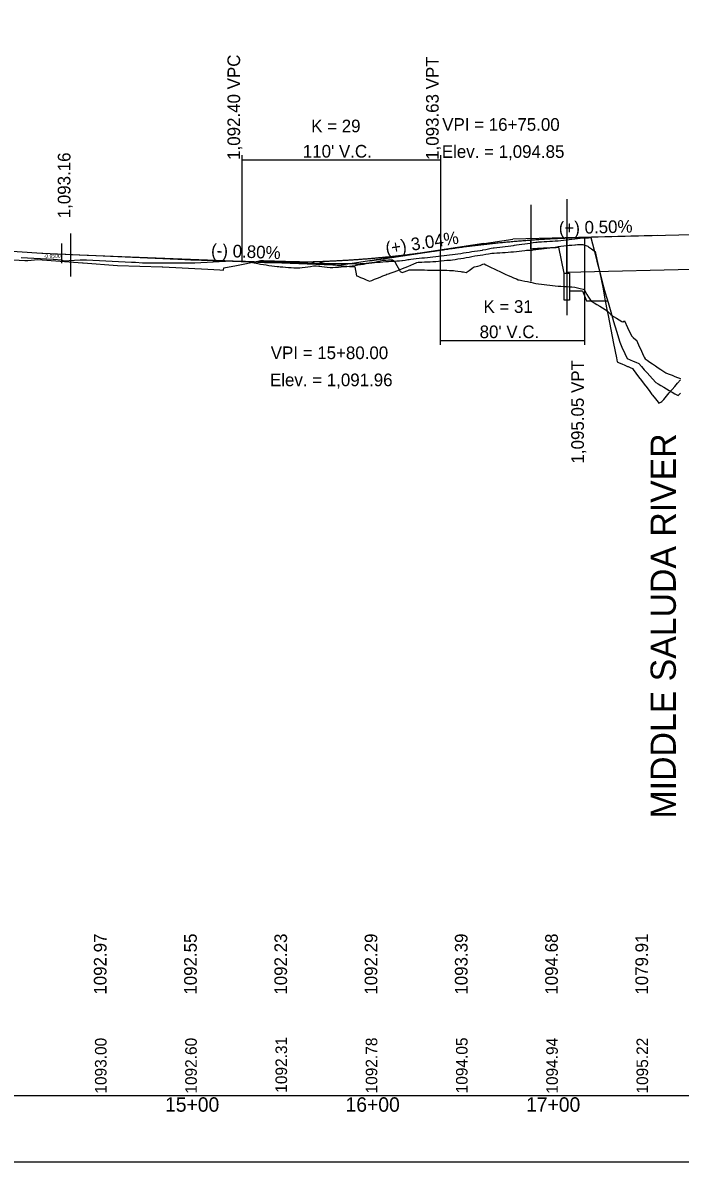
# Model space of a CAD drawing. Extents: x 1545155 to 1547500, y 1196198 to 1197298.
# Drawn here: x 1545559 to 1545923, y 1196198 to 1196829 of the extents above; entities that cross this region are included whole.
import ezdxf

# ---------------------------------------------------------------- set-up
doc = ezdxf.new("R2010")
doc.units = 0
for name, color, linetype in [('BR_CONCRETE', 7, 'Continuous'), ('BR_PROPOSED_TRAVELWAY', 7, 'Continuous'), ('RD_PD_ALT1_TX', 7, 'Continuous'), ('RD_PD_BOC', 7, 'Continuous'), ('RD_PD_CstnLmt', 7, 'Continuous'), ('RD_PD_DR_ErosCtrl', 7, 'Continuous'), ('RD_PD_Final_TrvlWay', 7, 'Continuous'), ('RD_PD_PaveShd', 7, 'Continuous'), ('RD_PD_RW_TX', 7, 'Continuous'), ('RD_SHT_IplotShp', 7, 'Continuous'), ('RD_SHT_ShtClip', 7, 'Continuous'), ('RD_Sketch1', 7, 'Continuous'), ('RD_Sketch2', 7, 'Continuous'), ('RD_Sketch8', 7, 'Continuous')]:
    doc.layers.add(name, color=color, linetype=linetype)

msp = doc.modelspace()

# ---------------------------------------------------------------- linework, layer by layer
at = {"layer": 'BR_CONCRETE'}
msp.add_lwpolyline([(1545544.44, 1196703.26), (1545569.25, 1196701.73), (1545569.73, 1196701.7), (1545594.31, 1196700.54), (1545594.64, 1196700.53), (1545595.08, 1196700.5), (1545619.42, 1196699.35), (1545644.41, 1196698.29), (1545645.07, 1196698.26), (1545651.75, 1196698.04), (1545669.53, 1196697.42), (1545670.23, 1196697.41), (1545688.8, 1196696.71), (1545690.34, 1196696.65), (1545691.88, 1196696.59), (1545692.6, 1196696.56), (1545693.42, 1196696.56), (1545694.99, 1196696.55), (1545696.5, 1196696.52), (1545698.04, 1196696.49), (1545699.58, 1196696.45), (1545701.12, 1196696.42), (1545702.66, 1196696.38), (1545704.2, 1196696.35), (1545705.74, 1196696.31), (1545707.28, 1196696.28), (1545708.82, 1196696.24), (1545710.36, 1196696.2), (1545711.9, 1196696.16), (1545713.44, 1196696.12), (1545714.98, 1196696.08), (1545716.52, 1196696.04), (1545717.54, 1196696.02), (1545718.06, 1196696.01), (1545718.74, 1196696.01), (1545719.6, 1196695.98), (1545720.08, 1196695.97), (1545721.14, 1196695.97), (1545722.68, 1196695.96), (1545724.22, 1196695.95), (1545725.76, 1196695.95), (1545727.3, 1196695.94), (1545728.84, 1196695.93), (1545730.38, 1196695.92), (1545731.92, 1196695.91), (1545733.46, 1196695.9), (1545735, 1196695.89), (1545736.54, 1196695.88), (1545738.08, 1196695.87), (1545739.62, 1196695.86), (1545741.16, 1196695.84), (1545742.7, 1196695.83), (1545744.24, 1196695.82), (1545744.71, 1196695.81), (1545745.07, 1196695.81), (1545745.78, 1196695.86), (1545747.32, 1196696), (1545748.86, 1196696.13), (1545750.4, 1196696.27), (1545751.94, 1196696.39), (1545753.48, 1196696.52), (1545755.02, 1196696.64), (1545756.56, 1196696.76), (1545758.1, 1196696.87), (1545759.64, 1196696.99), (1545761.18, 1196697.09), (1545762.72, 1196697.2), (1545764.26, 1196697.3), (1545765.8, 1196697.4), (1545767.34, 1196697.49), (1545768.55, 1196697.56), (1545768.88, 1196697.61), (1545770.42, 1196697.85), (1545771.96, 1196698.07), (1545772.73, 1196698.19), (1545773.5, 1196698.28), (1545775.04, 1196698.46), (1545776.58, 1196698.64), (1545778.12, 1196698.81), (1545779.66, 1196698.98), (1545781.2, 1196699.15), (1545782.74, 1196699.32), (1545784.28, 1196699.49), (1545785.82, 1196699.65), (1545787.36, 1196699.81), (1545788.9, 1196699.97), (1545790.44, 1196700.12), (1545791.99, 1196700.28), (1545793.53, 1196700.48), (1545795.07, 1196700.67), (1545796.61, 1196700.87), (1545798.16, 1196701.06), (1545799.69, 1196701.31), (1545801.23, 1196701.56), (1545802.77, 1196701.8), (1545804.31, 1196702.05), (1545805.85, 1196702.28), (1545807.39, 1196702.52), (1545808.93, 1196702.75), (1545810.47, 1196702.99), (1545812.01, 1196703.21), (1545813.21, 1196703.39), (1545813.55, 1196703.46), (1545815.09, 1196703.76), (1545816.63, 1196704.06), (1545818.17, 1196704.36), (1545819.27, 1196704.58), (1545819.79, 1196704.65), (1545821.25, 1196704.84), (1545822.79, 1196705.03), (1545824.33, 1196705.22), (1545825.87, 1196705.41), (1545827.41, 1196705.6), (1545828.95, 1196705.78), (1545830.49, 1196705.96), (1545830.99, 1196706.02), (1545832.03, 1196706.18), (1545833.57, 1196706.4), (1545835.11, 1196706.62), (1545836.65, 1196706.84), (1545838.19, 1196707.06), (1545839.73, 1196707.28), (1545841.27, 1196707.49), (1545842.81, 1196707.7), (1545843.6, 1196707.81), (1545844.35, 1196707.86), (1545845.89, 1196707.97), (1545847.43, 1196708.08), (1545848.97, 1196708.18), (1545850.51, 1196708.28), (1545852.05, 1196708.38), (1545853.59, 1196708.48), (1545855.13, 1196708.57), (1545856.67, 1196708.67), (1545858.21, 1196708.77), (1545859.75, 1196708.96), (1545861.29, 1196709.16), (1545862.83, 1196709.35), (1545864.37, 1196709.55), (1545865.91, 1196709.74), (1545867.45, 1196709.93), (1545868.58, 1196710.07), (1545868.99, 1196710.1), (1545869.47, 1196710.12), (1545870.53, 1196710.17), (1545872.07, 1196710.23), (1545872.52, 1196710.25), (1545873.34, 1196710.35), (1545875.15, 1196703.25), (1545876.69, 1196697.2), (1545878.23, 1196691.16), (1545879.99, 1196684.22), (1545881.31, 1196679.69), (1545882.85, 1196674.39), (1545884.39, 1196669.1), (1545885.93, 1196663.8), (1545887.47, 1196658.52), (1545889.28, 1196652.3), (1545890.55, 1196649.53), (1545892.09, 1196646.17), (1545893.43, 1196643.25), (1545895.17, 1196642.52), (1545896.71, 1196641.88), (1545898.25, 1196641.23), (1545899.87, 1196640.49), (1545901.33, 1196638.86), (1545902.87, 1196637.13), (1545904.41, 1196635.41), (1545905.95, 1196633.69), (1545907.49, 1196631.97), (1545909.25, 1196630.01), (1545910.57, 1196629.22), (1545912.11, 1196628.31), (1545913.65, 1196627.4), (1545915.19, 1196626.49), (1545916.73, 1196625.59), (1545918.27, 1196624.69), (1545919.81, 1196623.8), (1545921.6, 1196622.76), (1545922.89, 1196624.18)], dxfattribs=at)
at = {"layer": 'BR_PROPOSED_TRAVELWAY'}
msp.add_lwpolyline([(1545155, 1197298.22), (1546955, 1197298.22), (1546955, 1196198.22), (1545155, 1196198.22)], close=True, dxfattribs=at)
at = {"layer": 'RD_PD_ALT1_TX'}
msp.add_lwpolyline([(1545547.12, 1196698.3), (1545559.78, 1196697.58), (1545561.36, 1196697.58), (1545566.99, 1196698.17), (1545591.6, 1196696.23), (1545592.05, 1196696.27), (1545611.05, 1196694.79), (1545635.73, 1196694.16), (1545636.19, 1196694.13), (1545661.04, 1196692.75), (1545667.86, 1196692.37), (1545669.71, 1196692.32), (1545670.04, 1196693.57), (1545676.97, 1196694.79), (1545688.8, 1196697.23), (1545690.36, 1196697.58), (1545691.88, 1196697.53), (1545693.42, 1196697.48), (1545694.96, 1196697.43), (1545696.5, 1196697.39), (1545698.04, 1196697.34), (1545699.58, 1196697.29), (1545701.12, 1196697.25), (1545702.66, 1196697.2), (1545704.2, 1196697.16), (1545705.74, 1196697.12), (1545707.28, 1196697.07), (1545708.82, 1196697.03), (1545710.36, 1196696.99), (1545711.9, 1196696.95), (1545713.44, 1196696.91), (1545714.98, 1196696.86), (1545716.52, 1196696.82), (1545718.1, 1196696.78), (1545719.6, 1196696.31), (1545721.14, 1196695.8), (1545721.9, 1196695.53), (1545722.68, 1196695.33), (1545723.05, 1196695.23), (1545723.39, 1196696.57), (1545724.22, 1196696.43), (1545725.76, 1196696.17), (1545727.3, 1196695.91), (1545728.84, 1196695.65), (1545730.38, 1196695.4), (1545731.92, 1196695.14), (1545733.46, 1196694.88), (1545735.2, 1196694.59), (1545736.54, 1196694.5), (1545738.08, 1196694.41), (1545739.62, 1196694.31), (1545741.16, 1196694.22), (1545742.57, 1196694.14), (1545743.46, 1196689.15), (1545744.24, 1196688.83), (1545745.78, 1196688.19), (1545747.32, 1196687.54), (1545748.86, 1196686.88), (1545750.64, 1196686.1), (1545751.94, 1196686.58), (1545753.48, 1196687.17), (1545755.02, 1196687.77), (1545756.56, 1196688.39), (1545758.1, 1196689.03), (1545759.64, 1196689.68), (1545760.23, 1196689.94), (1545761.18, 1196690.26), (1545762.72, 1196690.79), (1545764.26, 1196691.34), (1545765.8, 1196691.9), (1545767.34, 1196692.48), (1545768.88, 1196693.07), (1545770.42, 1196693.69), (1545771.96, 1196694.32), (1545773.5, 1196694.96), (1545775.25, 1196695.72), (1545776.58, 1196696.36), (1545776.94, 1196696.53), (1545777.57, 1196696.72), (1545778.12, 1196696.72), (1545779.66, 1196696.75), (1545781.2, 1196696.8), (1545782.74, 1196696.85), (1545784.28, 1196696.93), (1545785.82, 1196697.02), (1545787.36, 1196697.12), (1545788.9, 1196697.24), (1545790.44, 1196697.38), (1545791.99, 1196697.52), (1545793.53, 1196697.69), (1545794.1, 1196697.76), (1545795.07, 1196697.83), (1545795.46, 1196697.86), (1545796.61, 1196698.01), (1545798.15, 1196698.22), (1545799.69, 1196698.45), (1545801.23, 1196698.7), (1545802.77, 1196698.96), (1545804.31, 1196699.23), (1545805.85, 1196699.52), (1545807.39, 1196699.83), (1545809.06, 1196700.18), (1545810.47, 1196700.37), (1545812.01, 1196700.58), (1545813.55, 1196700.8), (1545815.09, 1196701.03), (1545816.63, 1196701.27), (1545818.41, 1196701.59), (1545819.71, 1196701.66), (1545821.25, 1196701.76), (1545822.79, 1196701.86), (1545824.33, 1196701.97), (1545825.87, 1196702.08), (1545827.41, 1196702.21), (1545828.95, 1196702.34), (1545830.49, 1196702.48), (1545832.03, 1196702.63), (1545833.57, 1196702.79), (1545835.11, 1196702.95), (1545836.65, 1196703.12), (1545837.7, 1196703.24), (1545838.19, 1196703.26), (1545839.73, 1196703.32), (1545840.77, 1196703.37), (1545841.27, 1196703.43), (1545842.81, 1196703.61), (1545844.35, 1196703.8), (1545845.89, 1196703.99), (1545847.43, 1196704.19), (1545848.97, 1196704.4), (1545850.51, 1196704.61), (1545852.05, 1196704.82), (1545853.59, 1196705.04), (1545855.13, 1196705.27), (1545856.67, 1196705.5), (1545858.29, 1196705.76), (1545859.75, 1196705.88), (1545861.29, 1196706.02), (1545862.83, 1196706.16), (1545864.37, 1196706.3), (1545864.85, 1196706.35), (1545865.91, 1196706.39), (1545867.45, 1196706.47), (1545868.85, 1196706.54), (1545870.53, 1196705.9), (1545871.7, 1196705.46), (1545872.07, 1196705.19), (1545873.61, 1196704.08), (1545875.15, 1196703), (1545875.78, 1196702.56), (1545876.69, 1196698.19), (1545878.23, 1196690.76), (1545879.86, 1196682.89), (1545881.31, 1196675.24), (1545882.39, 1196669.54), (1545882.85, 1196667.19), (1545884.39, 1196659.36), (1545885.93, 1196651.54), (1545887.47, 1196643.73), (1545887.91, 1196641.47), (1545889.01, 1196640.99), (1545890.55, 1196640.32), (1545892.09, 1196639.65), (1545893.63, 1196638.98), (1545893.98, 1196638.83), (1545895.17, 1196638.3), (1545896.29, 1196637.79), (1545896.71, 1196637.24), (1545898.25, 1196635.2), (1545899.79, 1196633.15), (1545901.33, 1196631.11), (1545902.87, 1196629.07), (1545904.41, 1196627.04), (1545905.95, 1196625.01), (1545907.17, 1196623.4), (1545907.49, 1196623), (1545909.03, 1196621.05), (1545910.57, 1196619.1), (1545911.02, 1196618.53), (1545912.11, 1196619.16), (1545912.71, 1196619.51), (1545913.65, 1196620.62), (1545915.19, 1196622.44), (1545916.73, 1196624.26), (1545918.27, 1196626.07), (1545919.81, 1196627.88), (1545921.35, 1196629.69), (1545922.89, 1196631.5)], dxfattribs=at)
at = {"layer": 'RD_PD_BOC'}
for p, q in [((1545839.97, 1196704.11), (1545839.97, 1196708.96)), ((1545860, 1196691.01), (1545860, 1196710.1)), ((1545858.5, 1196690.6), (1545855.64, 1196704.94)), ((1545860, 1196691.07), (1545960, 1196693.57)), ((1545860, 1196691.01), (1545860, 1196690.6)), ((1545861.5, 1196680.78), (1545868.59, 1196680.78)), ((1545868.59, 1196680.78), (1545870.83, 1196675.18)), ((1545870.83, 1196675.18), (1545882.62, 1196675.18))]:
    msp.add_line(p, q, dxfattribs=at)
msp.add_lwpolyline([(1545858.5, 1196690.6), (1545861.5, 1196690.6), (1545861.5, 1196675.6), (1545858.5, 1196675.6)], close=True, dxfattribs=at)
msp.add_open_spline([(1545839.97, 1196704.11), (1545841.69, 1196704.22), (1545843.41, 1196704.33), (1545848.45, 1196704.62), (1545851.76, 1196704.78), (1545855.27, 1196704.92), (1545855.45, 1196704.93), (1545855.64, 1196704.94)], degree=3, dxfattribs=at)
at = {"layer": 'RD_PD_DR_ErosCtrl'}
for p, q in [((1545870, 1196710.43), (1545965, 1196712.8)), ((1545585, 1196700.98), (1545680, 1196697.18))]:
    msp.add_line(p, q, dxfattribs=at)
for points in [[(1545790, 1196703.34), (1545791.6, 1196703.59), (1545793.2, 1196703.82), (1545794.8, 1196704.06), (1545796.4, 1196704.28), (1545798, 1196704.51), (1545799.6, 1196704.73), (1545801.2, 1196704.95), (1545802.8, 1196705.16), (1545804.4, 1196705.37), (1545806, 1196705.57), (1545807.6, 1196705.77), (1545809.2, 1196705.97), (1545810.8, 1196706.16), (1545812.4, 1196706.35), (1545814, 1196706.54), (1545815.6, 1196706.72), (1545817.2, 1196706.89), (1545818.8, 1196707.07), (1545820.4, 1196707.23), (1545822, 1196707.4), (1545823.6, 1196707.56), (1545825.2, 1196707.71), (1545826.8, 1196707.87), (1545828.4, 1196708.01), (1545830, 1196708.16), (1545831.6, 1196708.3), (1545833.2, 1196708.43), (1545834.8, 1196708.56), (1545836.4, 1196708.69), (1545838, 1196708.81), (1545839.6, 1196708.93), (1545841.2, 1196709.05), (1545842.8, 1196709.16), (1545844.4, 1196709.27), (1545846, 1196709.37), (1545847.6, 1196709.47), (1545849.2, 1196709.56), (1545850.8, 1196709.65), (1545852.4, 1196709.74), (1545854, 1196709.82), (1545855.6, 1196709.9), (1545857.2, 1196709.98), (1545858.8, 1196710.05), (1545860.4, 1196710.11), (1545862, 1196710.18), (1545863.6, 1196710.24), (1545865.2, 1196710.29), (1545866.8, 1196710.34), (1545868.4, 1196710.39), (1545870, 1196710.43)], [(1545680, 1196697.18), (1545682.2, 1196697.09), (1545684.4, 1196697.02), (1545686.6, 1196696.95), (1545688.8, 1196696.89), (1545691, 1196696.84), (1545693.2, 1196696.8), (1545695.4, 1196696.77), (1545697.6, 1196696.74), (1545699.8, 1196696.73), (1545702, 1196696.72), (1545704.2, 1196696.72), (1545706.4, 1196696.73), (1545708.6, 1196696.75), (1545710.8, 1196696.77), (1545713, 1196696.81), (1545715.2, 1196696.85), (1545717.4, 1196696.9), (1545719.6, 1196696.96), (1545721.8, 1196697.03), (1545724, 1196697.11), (1545726.2, 1196697.19), (1545728.4, 1196697.29), (1545730.6, 1196697.39), (1545732.8, 1196697.5), (1545735, 1196697.62), (1545737.2, 1196697.75), (1545739.4, 1196697.88), (1545741.6, 1196698.03), (1545743.8, 1196698.18), (1545746, 1196698.34), (1545748.2, 1196698.51), (1545750.4, 1196698.69), (1545752.6, 1196698.88), (1545754.8, 1196699.07), (1545757, 1196699.28), (1545759.2, 1196699.49), (1545761.4, 1196699.71), (1545763.6, 1196699.94), (1545765.8, 1196700.17), (1545768, 1196700.42), (1545770.2, 1196700.67), (1545772.4, 1196700.94), (1545774.6, 1196701.21), (1545776.8, 1196701.49), (1545779, 1196701.78), (1545781.2, 1196702.07), (1545783.4, 1196702.38), (1545785.6, 1196702.69), (1545787.8, 1196703.01), (1545790, 1196703.34)]]:
    msp.add_spline(points, degree=3, dxfattribs=at)
at = {"layer": 'RD_PD_RW_TX'}
msp.add_lwpolyline([(1545557.72, 1196699.25), (1545575.47, 1196698.34), (1545575.77, 1196698.32), (1545580.07, 1196697.89), (1545581.16, 1196697.47), (1545590.41, 1196697.96), (1545593.98, 1196697.96), (1545618.92, 1196696.69), (1545621, 1196696.59), (1545624.9, 1196696.21), (1545645.05, 1196696.29), (1545649.89, 1196696.27), (1545654, 1196696.25), (1545674.31, 1196697.33), (1545675.07, 1196697.22), (1545681.9, 1196697.23), (1545688.8, 1196695.89), (1545690.34, 1196695.62), (1545691.88, 1196695.36), (1545693.42, 1196695.13), (1545694.96, 1196694.9), (1545696.5, 1196694.7), (1545698.04, 1196694.51), (1545699.58, 1196694.33), (1545700.47, 1196694.24), (1545701.12, 1196694.17), (1545702.66, 1196694.03), (1545704.2, 1196693.9), (1545705.74, 1196693.79), (1545707.28, 1196693.7), (1545708.82, 1196693.62), (1545710.36, 1196693.56), (1545712.03, 1196693.51), (1545713.44, 1196693.7), (1545714.98, 1196693.91), (1545716.52, 1196694.13), (1545718.06, 1196694.36), (1545719.6, 1196694.61), (1545720.31, 1196694.73), (1545721.14, 1196694.62), (1545722.68, 1196694.43), (1545724.22, 1196694.26), (1545725.76, 1196694.1), (1545727.3, 1196693.94), (1545728.84, 1196693.8), (1545729.85, 1196693.72), (1545730.38, 1196693.74), (1545731.92, 1196693.83), (1545733.46, 1196693.93), (1545735, 1196694.05), (1545736.54, 1196694.19), (1545738.08, 1196694.34), (1545739.62, 1196694.51), (1545741.16, 1196694.69), (1545742.7, 1196694.89), (1545744.24, 1196695.11), (1545745.78, 1196695.34), (1545747.32, 1196695.59), (1545748.86, 1196695.85), (1545750.4, 1196696.14), (1545751.94, 1196696.43), (1545753.48, 1196696.74), (1545755.02, 1196697.07), (1545756.56, 1196697.42), (1545758.28, 1196697.82), (1545759.64, 1196697.85), (1545761.18, 1196697.88), (1545762.72, 1196697.92), (1545763.38, 1196697.93), (1545764.44, 1196697.21), (1545765.8, 1196694.86), (1545767.34, 1196692.21), (1545767.75, 1196691.51), (1545768.75, 1196690.91), (1545770.42, 1196691.49), (1545770.81, 1196691.62), (1545771.96, 1196692.14), (1545772.66, 1196692.45), (1545773.5, 1196692.44), (1545775.04, 1196692.42), (1545776.58, 1196692.4), (1545778.12, 1196692.38), (1545779.66, 1196692.36), (1545781.2, 1196692.34), (1545782.74, 1196692.31), (1545783.98, 1196692.3), (1545784.28, 1196692.29), (1545785.82, 1196692.27), (1545787.36, 1196692.25), (1545788.9, 1196692.23), (1545790.44, 1196692.21), (1545791.99, 1196692.18), (1545793.53, 1196692.16), (1545795.07, 1196692.14), (1545796.61, 1196692.11), (1545797.28, 1196692.1), (1545798.15, 1196691.95), (1545799.69, 1196691.69), (1545801.23, 1196691.43), (1545801.79, 1196691.33), (1545802.82, 1196691.3), (1545804.31, 1196690.87), (1545805.85, 1196692.06), (1545807.39, 1196693.25), (1545808.29, 1196693.94), (1545808.93, 1196694.07), (1545810.7, 1196694.43), (1545812.01, 1196694.91), (1545813.55, 1196695.48), (1545814.12, 1196695.68), (1545815.09, 1196695.19), (1545816.63, 1196694.41), (1545818.17, 1196693.65), (1545819.71, 1196692.9), (1545821.25, 1196692.16), (1545822.79, 1196691.43), (1545824.33, 1196690.72), (1545825.87, 1196690.02), (1545827.41, 1196689.33), (1545828.95, 1196688.66), (1545830.49, 1196688), (1545832.03, 1196687.35), (1545833.09, 1196686.92), (1545833.57, 1196686.81), (1545835.11, 1196686.5), (1545836.65, 1196686.21), (1545838.19, 1196685.92), (1545839.73, 1196685.65), (1545840.03, 1196685.6), (1545841.27, 1196685.25), (1545842.81, 1196684.83), (1545844.35, 1196684.61), (1545845.89, 1196684.4), (1545847.43, 1196684.21), (1545848.97, 1196684.03), (1545850.51, 1196683.86), (1545852.05, 1196683.71), (1545853.59, 1196683.56), (1545855.13, 1196683.43), (1545856.67, 1196683.31), (1545858.21, 1196683.2), (1545859.75, 1196683.11), (1545861.29, 1196683.03), (1545862.83, 1196682.96), (1545864.37, 1196682.84), (1545865.91, 1196682.47), (1545867.45, 1196682.1), (1545868.99, 1196681.73), (1545869.61, 1196681.59), (1545870.53, 1196679.83), (1545871.08, 1196678.79), (1545872.07, 1196677.2), (1545873.39, 1196675.09), (1545875.15, 1196674.06), (1545876.69, 1196673.15), (1545878.23, 1196672.25), (1545879.77, 1196671.34), (1545881.31, 1196670.43), (1545881.66, 1196670.22), (1545882.85, 1196669.15), (1545884.39, 1196667.76), (1545885.34, 1196666.9), (1545885.93, 1196666.55), (1545887.47, 1196665.64), (1545889.01, 1196664.73), (1545890.55, 1196663.82), (1545890.99, 1196663.55), (1545891.9, 1196664.15), (1545893.63, 1196660.56), (1545895.17, 1196657.37), (1545896.01, 1196655.63), (1545896.71, 1196655.04), (1545898.25, 1196653.74), (1545898.66, 1196653.39), (1545899.79, 1196650.81), (1545901.33, 1196647.3), (1545902.43, 1196644.78), (1545902.87, 1196643.99), (1545903.3, 1196643.2), (1545904.41, 1196642.44), (1545905.95, 1196641.38), (1545907.49, 1196640.33), (1545909.03, 1196639.28), (1545910.57, 1196638.22), (1545912.11, 1196637.17), (1545913.65, 1196636.12), (1545914.75, 1196635.37), (1545915.19, 1196635.2), (1545916.73, 1196634.6), (1545918.27, 1196634.01), (1545919.81, 1196633.42), (1545921.35, 1196632.83), (1545922.89, 1196632.24)], dxfattribs=at)
at = {"layer": 'RD_SHT_IplotShp'}
for p, q in [((1545814.09, 1196707.01), (1545735, 1196694.98)), ((1545750.91, 1196697.4), (1545830, 1196709.43)), ((1545909.98, 1196711.43), (1545830, 1196709.43)), ((1545655.07, 1196698.18), (1545735, 1196694.98))]:
    msp.add_line(p, q, dxfattribs=at)
at = {"layer": 'RD_SHT_ShtClip'}
for p, q in [((1545840, 1196728.39), (1545840, 1196686.21)), ((1545860, 1196731.49), (1545860, 1196667.24)), ((1545580, 1196707), (1545580, 1196696.19)), ((1545585, 1196712.5), (1545585, 1196688.72)), ((1545580, 1196701.22), (1545585, 1196700.98))]:
    msp.add_line(p, q, dxfattribs=at)
at = {"layer": 'RD_Sketch2'}
msp.add_line((1545155, 1196235.18), (1547500.39, 1196235.18), dxfattribs=at)
at = {"layer": 'RD_Sketch8'}
for p, q in [((1545680, 1196755.84), (1545680, 1196697.18)), ((1545680, 1196753.34), (1545790, 1196753.34)), ((1545790, 1196755.84), (1545790, 1196703.34)), ((1545870, 1196650.84), (1545870, 1196710.43)), ((1545790, 1196650.84), (1545790, 1196703.34)), ((1545790, 1196653.34), (1545870, 1196653.34))]:
    msp.add_line(p, q, dxfattribs=at)

# ---------------------------------------------------------------- texts
at = {"layer": 'RD_PD_CstnLmt'}
for s, p in [('15+00', (1545637.41, 1196226.18)), ('16+00', (1545737.41, 1196226.18)), ('17+00', (1545837.41, 1196226.18))]:
    msp.add_text(s, height=8, dxfattribs=at).set_placement(p)
at = {"layer": 'RD_PD_Final_TrvlWay'}
for s, height, p in [('1,092.40 VPC', 7, (1545679, 1196753.34)), ('1,093.63 VPT', 7, (1545789, 1196753.34)), ('1,095.05 VPT', 7, (1545869.45, 1196585.17)), ('1092.97', 7, (1545605, 1196291.02)), ('1092.55', 7, (1545655, 1196291.02)), ('1092.23', 7, (1545705, 1196291.02)), ('1092.29', 7, (1545755, 1196291.02)), ('1093.39', 7, (1545805, 1196291.02)), ('1094.68', 7, (1545855, 1196291.02)), ('1079.91', 7, (1545905, 1196291.02)), ('1093.00', 6.4, (1545605, 1196236.18)), ('1092.60', 6.4, (1545655, 1196236.18)), ('1092.31', 6.4, (1545705, 1196236.7)), ('1092.78', 6.4, (1545755, 1196236.31)), ('1094.05', 6.4, (1545805, 1196236.36)), ('1094.94', 6.4, (1545855, 1196236.18)), ('1095.22', 6.4, (1545905, 1196236.22))]:
    msp.add_text(s, height=height, rotation=90, dxfattribs=at).set_placement(p)
at = {"layer": 'RD_PD_PaveShd'}
for s, p in [('VPI = 16+75.00', (1545790.98, 1196769.43)), ('Elev. = 1,094.85', (1545790.74, 1196754.43)), ('VPI = 15+80.00', (1545695.98, 1196642.98)), ('Elev. = 1,091.96', (1545695.54, 1196627.98))]:
    msp.add_text(s, height=7, dxfattribs=at).set_placement(p)
msp.add_text('1,093.16', height=7, rotation=90, dxfattribs=at).set_placement((1545585, 1196720.98))
at = {"layer": 'RD_SHT_IplotShp'}
for s, rotation, p in [('(+) 0.50%', 1.4321, (1545855.62, 1196712.07)), ('(+) 3.04%', 8.64832, (1545760.08, 1196700.82)), ('(-) 0.80%', 357.70939, (1545662.82, 1196699.87))]:
    msp.add_text(s, height=7, rotation=rotation, dxfattribs=at).set_placement(p)
at = {"layer": 'RD_SHT_ShtClip'}
msp.add_text('-0.9500', height=2, dxfattribs=at).set_placement((1545570.21, 1196699.07))
at = {"layer": 'RD_Sketch1'}
msp.add_text('MIDDLE SALUDA RIVER', height=14, rotation=90, dxfattribs=at).set_placement((1545920.39, 1196388.6))
at = {"layer": 'RD_Sketch8'}
for s, p in [('K = 29', (1545718.38, 1196768.59)), ("110' V.C.", (1545713.75, 1196754.59)), ('K = 31', (1545813.81, 1196668.59)), ("80' V.C.", (1545811.69, 1196654.59))]:
    msp.add_text(s, height=7, dxfattribs=at).set_placement(p)

doc.saveas('drawing.dxf')
